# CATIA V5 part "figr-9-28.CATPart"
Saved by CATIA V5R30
Part number: Part1
Bounding box of the stored display mesh (mm): x -75 to 75, y -50 to 50, z 0 to 40
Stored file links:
  D:\PROJECTS\CATIA V56R 2020\Resources\Parts File\c09_catia_v5_6r2020_prt\figr-9-28.CATPart
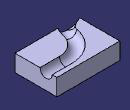
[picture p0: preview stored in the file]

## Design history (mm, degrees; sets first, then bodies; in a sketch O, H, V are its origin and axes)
Body1 (main body)
  Sketch1 on xy-plane, origin (0, 0, 0), H (1, 0, 0), V (0, 1, 0)
    line L1 (-75, 50) -> (75, 50)
    line L2 (75, 50) -> (75, -50)
    line L3 (75, -50) -> (-75, -50)
    line L4 (-75, -50) -> (-75, 50)
    axis line L5 (75, -50) -> (-75, 50)
    length L2 = 100
    length L3 = 150
    horizontal: L1 H, L3 H
    vertical: L2 V, L4 V
    midpoint: O L5
  Pad1: profile Sketch1, direction (0, 0, 1), length 40
  Sketch2 on face of Pad1, origin (75, 0, 0), H (0, 1, 0), V (0, 0, 1)
    arc A1 centre (24.1478, 40) radius 14.6047 from (9.543, 40) to (38.7525, 40) ccw
    point P1 (24.1478, 40)
    reference projected point E1 (24.1478, 40) from vertex of Sketch3
    line L1 (9.543, 40) -> (38.7525, 40)
    coincidence: P1 E1
    horizontal: L1 H
  Sketch3 on face of Pad1, origin (0, 0, 40), H (1, 0, 0), V (0, 1, 0)
    point P1 (75, 24.1478)
    line L1 (75, 24.1478) -> (28.6577, 24.1478)
    arc A1 centre (28.6577, -39.2062) radius 63.354 from (28.6577, 24.1478) to (-33.8383, -28.8149) ccw
    arc A2 centre (-62.192, -24.1005) radius 28.7429 from (-33.8383, -28.8149) to (-49.7271, -50) cw
    point P6 (-49.7271, -50)
    reference projected line E1 (75, -50) -> (75, 50) from edge [face of Pad1 | face of Pad1]
    reference projected line E2 (-75, -50) -> (75, -50) from edge [face of Pad1 | face of Pad1]
    horizontal: L1 H
    tangency: A1 L1, A2 A1
    coincidence: P1 E1, P6 E2
  Slot1: profile Sketch2, centre curve Sketch3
